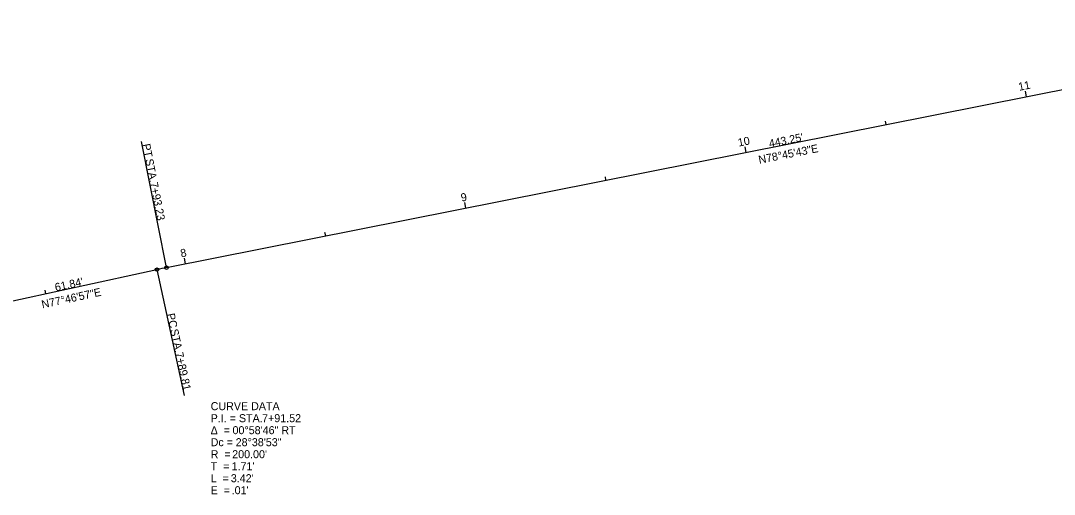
# Model space of a CAD drawing. Extents: x 1749457 to 1750917, y -159140 to -158804.
# Drawn here: x 1750193.5 to 1750555.2, y -159071.1 to -158905.4 of the extents above; entities that cross this region are included whole.
import ezdxf

# ---------------------------------------------------------------- set-up
doc = ezdxf.new("R2010")
doc.units = 0
for name, color, linetype in [('ALIGN', 7, 'Continuous'), ('C-STM STR', 7, 'Continuous'), ('SRF', 7, 'Continuous'), ('SRF-CONT EG MAJ', 7, 'Continuous'), ('SRF-CONT EG MIN', 7, 'Continuous'), ('TEXT', 7, 'Continuous')]:
    doc.layers.add(name, color=color, linetype=linetype)

msp = doc.modelspace()

# ---------------------------------------------------------------- linework, layer by layer
at = {"layer": 'ALIGN'}
for p, q in [((1750244.54, -158991.79), (1750679.29, -158905.4)), ((1750180.76, -159005.57), (1750241.19, -158992.48))]:
    msp.add_line(p, q, dxfattribs=at)
msp.add_arc((1750283.51, -159187.95), 200, 101.238, 102.2175, dxfattribs=at)
at = {"layer": 'SRF'}
for p, q in [((1750244.54, -158991.79), (1750235.77, -158947.65)), ((1750241.19, -158992.48), (1750250.71, -159036.46))]:
    msp.add_line(p, q, dxfattribs=at)
for centre in [(1750241.19, -158992.48), (1750244.54, -158991.79)]:
    msp.add_circle(centre, 0.6, dxfattribs=at)
at = {"layer": 'SRF-CONT EG MIN'}
for p, q in [((1750545.42, -158932), (1750545.03, -158930.04)), ((1750496.38, -158941.75), (1750496.15, -158940.57)), ((1750447.34, -158951.49), (1750446.95, -158949.53)), ((1750398.3, -158961.24), (1750398.07, -158960.06)), ((1750349.26, -158970.98), (1750348.87, -158969.02)), ((1750300.22, -158980.72), (1750299.98, -158979.55)), ((1750251.18, -158990.47), (1750250.79, -158988.51)), ((1750202.28, -159000.91), (1750202.02, -158999.73))]:
    msp.add_line(p, q, dxfattribs=at)

# ---------------------------------------------------------------- texts
at = {"layer": 'C-STM STR'}
for s, rotation, p in [('N78°45\'43"E', 11.238, (1750451.94, -158955.47)), ('N77°46\'57"E', 12.2175, (1750201.12, -159006.07))]:
    msp.add_text(s, height=2.8, rotation=rotation, dxfattribs=at).set_placement(p)
at = {"layer": 'SRF'}
for s, rotation, p in [('PT', 281.238, (1750236.02, -158948.71)), (' STA. ', 281.238, (1750236.86, -158952.98)), ('7+93.23', 281.238, (1750238.68, -158962.13)), ('PC', 282.2175, (1750244.6, -159008.06)), (' STA. ', 282.2175, (1750245.57, -159012.55)), ('7+89.81', 282.2175, (1750247.55, -159021.66))]:
    msp.add_text(s, height=2.8, rotation=rotation, dxfattribs=at).set_placement(p)
at = {"layer": 'SRF-CONT EG MAJ'}
for s, p in [('CURVE DATA', (1750259.98, -159041.65)), ('P.I. = STA. ', (1750259.98, -159045.85)), ('7+91.52', (1750277.97, -159045.85)), ('Δ  = ', (1750259.98, -159050.05)), ('00°58\'46" RT', (1750267.63, -159050.05)), ('Dc = ', (1750259.98, -159054.25)), ('28°38\'53"', (1750268.73, -159054.25)), ('R  = ', (1750259.98, -159058.45)), ("200.00'", (1750267.52, -159058.45)), ('T  = ', (1750259.98, -159062.65)), ("1.71'", (1750267.3, -159062.65)), ('L  = ', (1750259.98, -159066.85)), ("3.42'", (1750267.02, -159066.85)), (".01'", (1750267.33, -159071.05)), ('E  = ', (1750259.98, -159071.05))]:
    msp.add_text(s, height=2.8, dxfattribs=at).set_placement(p)
at = {"layer": 'SRF-CONT EG MIN'}
for s, p in [('11', (1750542.87, -158929.96)), ('10', (1750444.74, -158949.46)), ('9', (1750347.8, -158968.72)), ('8', (1750249.69, -158988.21))]:
    msp.add_text(s, height=2.8, rotation=11.238, dxfattribs=at).set_placement(p)
at = {"layer": 'TEXT'}
for s, rotation, p in [("443.25'", 11.238, (1750455.59, -158949.81)), ("61.84'", 12.2175, (1750205.77, -159000.11))]:
    msp.add_text(s, height=2.8, rotation=rotation, dxfattribs=at).set_placement(p)

doc.saveas('drawing.dxf')
